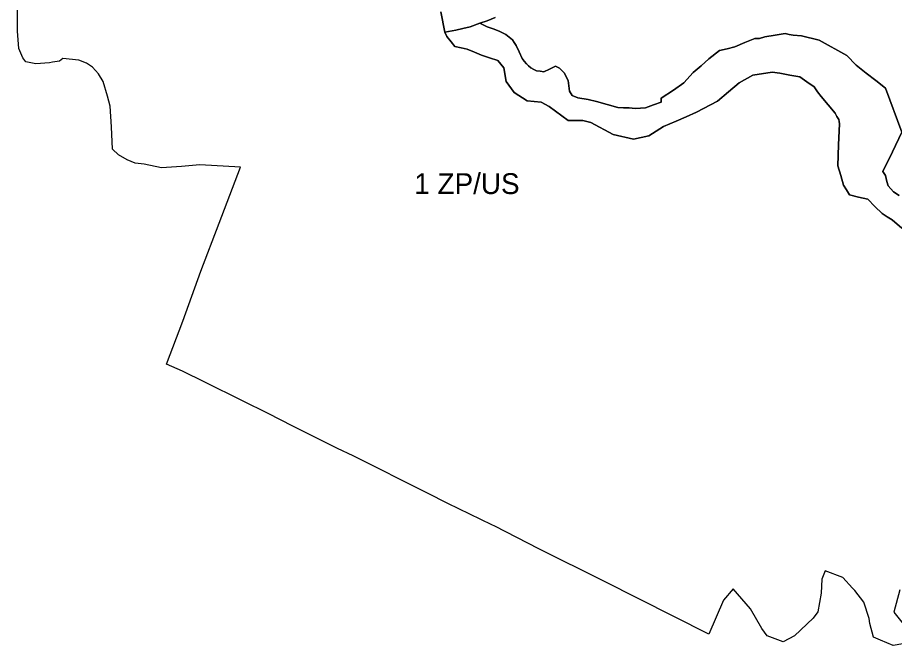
# Model space of a CAD drawing. Extents: x -294445 to -292055, y 21869 to 23693.
# Drawn here: x -294416.8 to -293995.9, y 22170.2 to 22471.6 of the extents above; entities that cross this region are included whole.
import ezdxf

# ---------------------------------------------------------------- set-up
doc = ezdxf.new("R2010")
doc.units = 0
doc.layers.add('linie_rozgraniczajace', color=7, linetype='Continuous')
doc.layers.add('oznaczenia_przeznaczen', color=7, linetype='Continuous')

msp = doc.modelspace()

# ---------------------------------------------------------------- linework, layer by layer
at = {"layer": 'linie_rozgraniczajace'}
for points in [[(-294329.35, 22400.81), (-294338.13, 22400.09), (-294347.78, 22399.49), (-294356.04, 22401.2), (-294360.32, 22401.63), (-294364.25, 22403.22), (-294368.41, 22405.59), (-294371.22, 22408.41), (-294371.66, 22419.07), (-294372.34, 22429.01), (-294373.71, 22433.75), (-294375.75, 22440.92), (-294378.03, 22444.49), (-294380.83, 22447.75), (-294383.75, 22449.63), (-294387.35, 22451.11), (-294395.09, 22451.88), (-294396.67, 22450.67), (-294400, 22450.07), (-294401.55, 22449.79), (-294408.04, 22449.28), (-294412.81, 22450.22), (-294414.27, 22452.17), (-294416.25, 22456.67), (-294416.83, 22465.07), (-294416.79, 22476.66)], [(-294213.715, 22474.306), (-294211.668, 22464.48), (-294210.72, 22462.47), (-294208.697, 22459.891), (-294206.94, 22457.65), (-294203.945, 22457.045), (-294200.95, 22456.44), (-294197.545, 22454.99), (-294194.14, 22453.54), (-294190.25, 22452.24), (-294186.36, 22450.94), (-294183.37, 22447.41), (-294182.25, 22440.82), (-294178.37, 22435.61), (-294172.13, 22431.5), (-294165.55, 22430.96), (-294161.66, 22428.9), (-294152.45, 22422.19), (-294145.48, 22422.07), (-294141.67, 22421.15), (-294130.96, 22415.35), (-294121.12, 22413.1), (-294113.726, 22414.831), (-294106.74, 22419.21), (-294100.74, 22421.77), (-294095.805, 22423.935), (-294090.87, 22426.1), (-294080.81, 22431.47), (-294075.63, 22435.875), (-294070.45, 22440.28), (-294063.94, 22443.83), (-294054.54, 22445.27), (-294050.99, 22444.84), (-294046.145, 22443.96), (-294041.3, 22443.08), (-294037.88, 22440.705), (-294034.46, 22438.33), (-294032.785, 22435.955), (-294031.11, 22433.58), (-294027.735, 22429.62), (-294024.36, 22425.66), (-294023.515, 22424.125), (-294022.67, 22422.59), (-294022.48, 22421.58), (-294022.29, 22420.57), (-294022.7, 22410.5)], [(-294187.571, 22471.638), (-294191.335, 22470.037), (-294194.872, 22468.799), (-294199.551, 22467.161), (-294203.013, 22466.357), (-294206.475, 22465.552), (-294211.668, 22464.48), (-294213.715, 22474.306)], [(-294194.872, 22468.799), (-294191.335, 22470.037), (-294187.571, 22471.638)], [(-294211.668, 22464.48), (-294206.475, 22465.552), (-294203.013, 22466.357), (-294199.551, 22467.161), (-294194.872, 22468.799), (-294191.39, 22467.11), (-294188.535, 22466.08), (-294185.68, 22465.05), (-294182.48, 22463.45), (-294180.89, 22462.165), (-294179.3, 22460.88), (-294178.365, 22459.495), (-294177.43, 22458.11), (-294176.01, 22455.015), (-294174.59, 22451.92), (-294173.585, 22450.645), (-294172.58, 22449.37), (-294171.495, 22448.365), (-294170.41, 22447.36), (-294169.065, 22446.68), (-294167.72, 22446), (-294165.945, 22445.77), (-294164.17, 22445.54), (-294161.42, 22446.84), (-294158.67, 22448.14), (-294157.685, 22447.725), (-294156.7, 22447.31), (-294155.53, 22446.105), (-294154.36, 22444.9), (-294153.43, 22443.1), (-294152.5, 22441.3), (-294152.22, 22438.765), (-294151.94, 22436.23), (-294150.56, 22434.19), (-294147.96, 22433.01), (-294142.9, 22432.18), (-294138.96, 22431.24), (-294133.81, 22429.785), (-294128.66, 22428.33), (-294125.97, 22428.245), (-294123.28, 22428.16), (-294120.33, 22427.94), (-294117.87, 22428.095), (-294115.41, 22428.25), (-294111.64, 22429.585), (-294107.87, 22430.92), (-294107.84, 22432.87), (-294102.03, 22436.7), (-294097.05, 22440.27), (-294092.52, 22445.21), (-294088.755, 22448.445), (-294084.99, 22451.68), (-294079.82, 22455.69), (-294076.13, 22456.59), (-294072.44, 22457.49), (-294067.645, 22459.53), (-294062.85, 22461.57), (-294060.73, 22461.57), (-294058.06, 22462.29), (-294053.205, 22463.065), (-294048.35, 22463.84), (-294046.45, 22463.46), (-294044.55, 22463.08), (-294040.49, 22462.82), (-294032.02, 22460.77), (-294018.836, 22453.333), (-294014.273, 22448.71), (-294009.42, 22444.91), (-294004.83, 22441.32), (-294000.24, 22437.73), (-293992.35, 22416.5), (-293996.895, 22407.1), (-294001.44, 22397.7), (-294000.2, 22395.77), (-293999.63, 22392.78), (-293998.86, 22390.75), (-293997.635, 22389.36), (-293996.41, 22387.97), (-293993.655, 22386.175)], [(-293993.655, 22386.175), (-293996.41, 22387.97), (-293997.635, 22389.36), (-293998.86, 22390.75), (-293999.63, 22392.78), (-294000.2, 22395.77), (-294001.44, 22397.7), (-293996.895, 22407.1), (-293992.35, 22416.5), (-294000.24, 22437.73), (-294004.83, 22441.32), (-294009.42, 22444.91), (-294014.273, 22448.71), (-294018.836, 22453.333), (-294032.02, 22460.77), (-294040.49, 22462.82), (-294044.55, 22463.08), (-294046.45, 22463.46), (-294048.35, 22463.84), (-294053.205, 22463.065), (-294058.06, 22462.29), (-294060.73, 22461.57), (-294062.85, 22461.57), (-294067.645, 22459.53), (-294072.44, 22457.49), (-294076.13, 22456.59), (-294079.82, 22455.69), (-294084.99, 22451.68), (-294088.755, 22448.445), (-294092.52, 22445.21), (-294097.05, 22440.27), (-294102.03, 22436.7), (-294107.84, 22432.87), (-294107.87, 22430.92), (-294111.64, 22429.585), (-294115.41, 22428.25), (-294117.87, 22428.095), (-294120.33, 22427.94), (-294123.28, 22428.16), (-294125.97, 22428.245), (-294128.66, 22428.33), (-294133.81, 22429.785), (-294138.96, 22431.24), (-294142.9, 22432.18), (-294147.96, 22433.01), (-294150.56, 22434.19), (-294151.94, 22436.23), (-294152.22, 22438.765), (-294152.5, 22441.3), (-294153.43, 22443.1), (-294154.36, 22444.9), (-294155.53, 22446.105), (-294156.7, 22447.31), (-294157.685, 22447.725), (-294158.67, 22448.14), (-294161.42, 22446.84), (-294164.17, 22445.54), (-294165.945, 22445.77), (-294167.72, 22446), (-294169.065, 22446.68), (-294170.41, 22447.36), (-294171.495, 22448.365), (-294172.58, 22449.37), (-294173.585, 22450.645), (-294174.59, 22451.92), (-294176.01, 22455.015), (-294177.43, 22458.11), (-294178.365, 22459.495), (-294179.3, 22460.88), (-294180.89, 22462.165), (-294182.48, 22463.45), (-294185.68, 22465.05), (-294188.535, 22466.08), (-294191.39, 22467.11), (-294194.872, 22468.799)], [(-294022.29, 22420.57), (-294022.48, 22421.58), (-294022.67, 22422.59), (-294023.515, 22424.125), (-294024.36, 22425.66), (-294027.735, 22429.62), (-294031.11, 22433.58), (-294032.785, 22435.955), (-294034.46, 22438.33), (-294037.88, 22440.705), (-294041.3, 22443.08), (-294046.145, 22443.96), (-294050.99, 22444.84), (-294054.54, 22445.27), (-294063.94, 22443.83), (-294070.45, 22440.28), (-294075.63, 22435.875), (-294080.81, 22431.47), (-294090.87, 22426.1), (-294095.805, 22423.935), (-294100.74, 22421.77), (-294106.74, 22419.21), (-294113.726, 22414.831), (-294121.12, 22413.1), (-294130.96, 22415.35), (-294141.67, 22421.15), (-294145.48, 22422.07), (-294152.45, 22422.19), (-294161.66, 22428.9), (-294165.55, 22430.96), (-294172.13, 22431.5), (-294178.37, 22435.61), (-294182.25, 22440.82), (-294183.37, 22447.41), (-294186.36, 22450.94), (-294190.25, 22452.24), (-294194.14, 22453.54), (-294197.545, 22454.99), (-294200.95, 22456.44), (-294203.945, 22457.045), (-294206.94, 22457.65), (-294208.697, 22459.891), (-294210.72, 22462.47), (-294211.668, 22464.48)], [(-293992.35, 22370.48), (-293997.05, 22374.42), (-293999.455, 22375.94), (-294001.86, 22377.46), (-294005.28, 22380.895), (-294008.7, 22384.33), (-294013.12, 22385.39), (-294017.54, 22386.45), (-294018.915, 22388.805), (-294020.29, 22391.16), (-294021.7, 22395.795), (-294023.11, 22400.43), (-294022.7, 22410.5), (-294022.29, 22420.57)], [(-294022.7, 22410.5), (-294023.11, 22400.43), (-294021.7, 22395.795), (-294020.29, 22391.16), (-294018.915, 22388.805), (-294017.54, 22386.45), (-294013.12, 22385.39), (-294008.7, 22384.33), (-294005.28, 22380.895), (-294001.86, 22377.46), (-293999.455, 22375.94), (-293997.05, 22374.42), (-293992.35, 22370.48)], [(-293991.83, 22170.9), (-293996.59, 22170.18), (-294002.6, 22172.75), (-294005.94, 22174.17), (-294007.64, 22180.64), (-294008, 22183.19), (-294010.53, 22190.94), (-294014.84, 22196.51), (-294015.96, 22197.69), (-294020.65, 22202.79), (-294029.21, 22205.94), (-294030.73, 22202.05), (-294031.05, 22195.3), (-294032.74, 22186.37), (-294034.95, 22183.26), (-294043.87, 22174.82), (-294049.37, 22171.85), (-294057.03, 22174.87), (-294059.61, 22178.33), (-294064.98, 22187.73), (-294073.31, 22197.41), (-294078.01, 22191.87), (-294085.08, 22175.6), (-294135.47, 22201.11), (-294166.63, 22216.57), (-294187.78, 22227.43), (-294189.19, 22228.15), (-294210.32, 22238.27), (-294220.08, 22243.34), (-294255.76, 22261.24), (-294263.19, 22264.77), (-294284.67, 22275.44), (-294296.52, 22281.53), (-294308.86, 22287.51), (-294326.96, 22296.47), (-294337.63, 22301.75), (-294345.27, 22305.16), (-294337.55, 22325.76), (-294328.81, 22349.78), (-294319.97, 22372.93), (-294309.8, 22399.77), (-294329.35, 22400.81)], [(-293993.27, 22196.94), (-293996.21, 22186.18), (-293987.7, 22175.54)]]:
    msp.add_lwpolyline(points, dxfattribs=at)

# ---------------------------------------------------------------- texts
at = {"layer": 'oznaczenia_przeznaczen'}
msp.add_text('1 ZP/US', height=10, dxfattribs=at).set_placement((-294226.378, 22386.831))

doc.saveas('drawing.dxf')
